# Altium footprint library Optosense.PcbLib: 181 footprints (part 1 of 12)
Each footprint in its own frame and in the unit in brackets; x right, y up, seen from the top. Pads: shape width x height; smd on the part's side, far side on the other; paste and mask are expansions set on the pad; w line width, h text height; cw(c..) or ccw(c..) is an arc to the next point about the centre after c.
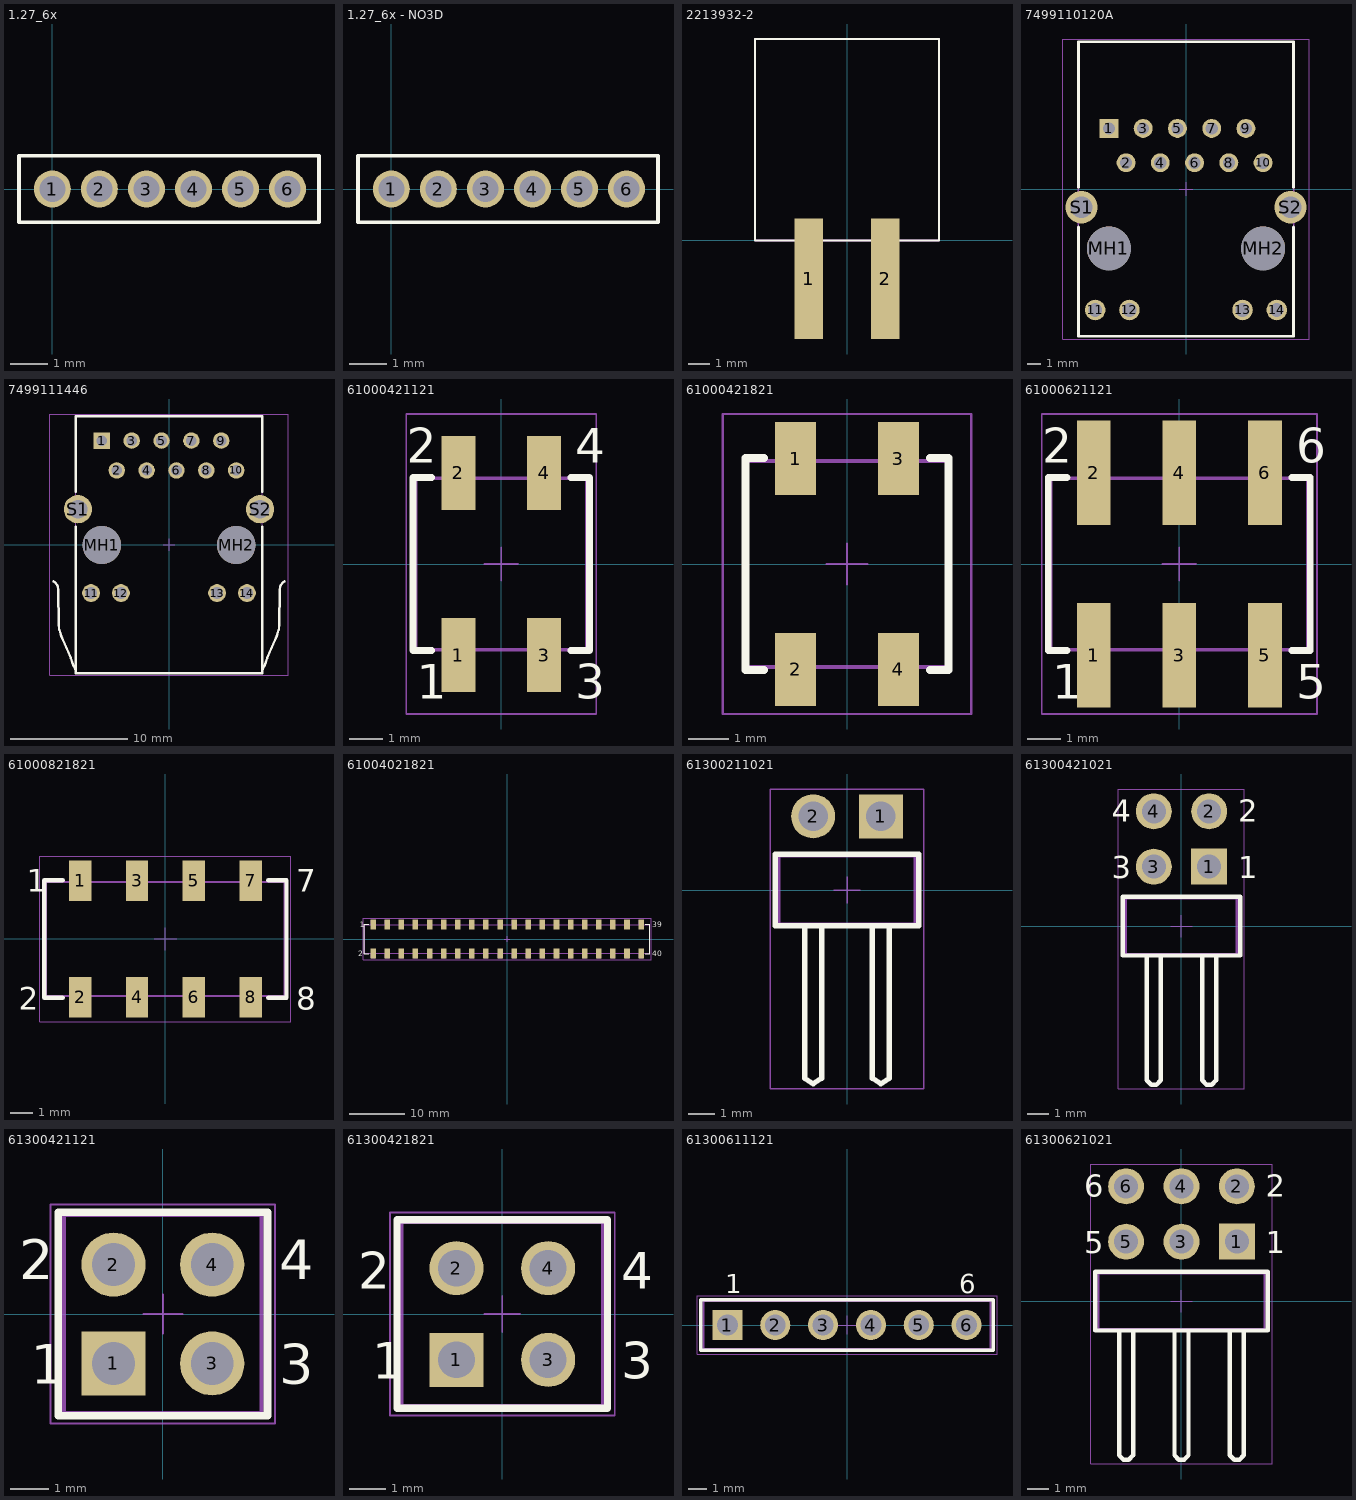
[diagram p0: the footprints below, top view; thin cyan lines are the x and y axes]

## 1.27_6x [mm]
pads (6):
  round 1 hole 0.7: 1(0,0) 2(1.27,0) 3(2.54,0) 4(3.81,0) 5(5.08,0) 6(6.35,0)
Top Overlay:
  lines w0.1: -0.9,-0.9 -0.9,0.9 ; -0.9,-0.9 7.2,-0.9 7.2,0.9 -0.9,0.9 ; -0.9,-0.9 -0.9,0.9
3D body "User Library-PLLR-6.step": height 2.35, standoff -2.45, extent -0.635,-0.2 6.985,6

## 1.27_6x - NO3D [mm]
pads (6):
  round 1 hole 0.7: 1(0,0) 2(1.27,0) 3(2.54,0) 4(3.81,0) 5(5.08,0) 6(6.35,0)
Top Overlay:
  lines w0.1: -0.9,-0.9 -0.9,0.9 ; -0.9,-0.9 7.2,-0.9 7.2,0.9 -0.9,0.9 ; -0.9,-0.9 -0.9,0.9

## 2213932-2 [mm]
pads (2):
  rect 1.3x5.5 smd paste+0 mask+0: 1(-1.75,-1.75) 2(1.75,-1.75)
Top Overlay:
  lines w0.1: -4.2,0 4.2,0 4.2,9.2 -4.2,9.2 -4.2,0
Mechanical 15:
  lines w0.1: -4.2,0 0,0 4.2,0 4.2,9.2 -4.2,9.2 -4.2,0
3D body "c-2213932-2-1-3d.stp": height 7.35, standoff 0.05, extent -4.2,-3.5 4.2,9.2

## 7499110120A [mm] "LAN Transformer, body 21.84x15.95mm"
height 16.9
pads (18):
  rect 1.4x1.4 hole 0.9: 1(-5.715,4.49)
  round 1.4 hole 0.9: 2(-4.445,1.95) 3(-3.175,4.49) 4(-1.905,1.95) 5(-0.635,4.49) 6(0.635,1.95) 7(1.905,4.49) 8(3.175,1.95) 9(4.445,4.49) 10(5.715,1.95)
  round 1.52 hole 1.02: 11(-6.73,-8.97) 12(-4.19,-8.97) 13(4.19,-8.97) 14(6.73,-8.97)
  round 3.25 hole 3.25 unplated: MH1(-5.715,-4.4) MH2(5.715,-4.4)
  round 2.4 hole 1.6: S1(-7.745,-1.35) S2(7.745,-1.35)
Top Overlay:
  lines w0.2: -7.975,-2.82 -7.975,-10.92 7.975,-10.92 7.975,-2.82 ; -7.975,0.12 -7.975,10.92 7.975,10.92 7.975,0.12
Mechanical 13:
  lines w0.1: -7.975,-10.92 7.975,-10.92 7.975,10.92 -7.975,10.92 -7.975,-10.92
Mechanical 15:
  lines w0.05: -0.5,0 0.5,0 ; 0,-0.5 0,0.5 ; -9.145,-11.12 -9.145,11.12 9.145,11.12 9.145,-11.12 -9.145,-11.12
3D body "7499110120A.stp": height 16.87, standoff -3.32, extent -8.1,-10.92 8.1,10.92

## 7499111446 [mm] "LAN Transformer, body 21.84x15.88mm"
height 13.95
pads (18):
  rect 1.4x1.4 hole 0.9: 1(-5.715,8.86)
  round 1.4 hole 0.9: 2(-4.445,6.32) 3(-3.175,8.86) 4(-1.905,6.32) 5(-0.635,8.86) 6(0.635,6.32) 7(1.905,8.86) 8(3.175,6.32) 9(4.445,8.86) 10(5.715,6.32)
  round 1.52 hole 1.02: 11(-6.63,-4.11) 12(-4.09,-4.11) 13(4.09,-4.11) 14(6.63,-4.11)
  round 3.25 hole 3.25 unplated: MH1(-5.715,-0.03) MH2(5.715,-0.03)
  round 2.4 hole 1.6: S1(-7.745,3.02) S2(7.745,3.02)
Top Overlay:
  lines w0.2: -9.83,-3.109 cw(c-10.225,-3.801) -9.428,-3.801 -9.37,-6.9 ccw(c-8.1,-6.9) -9.27,-7.394 ccw(c-6.8,-6.9) -9.012,-8.105 -8.345,-9.664 ccw(c-2,-7.78) -7.94,-10.7 ; -7.94,1.53 -7.94,-10.92 7.94,-10.92 7.94,1.53 ; -7.94,4.48 -7.94,10.92 7.94,10.92 7.94,4.48 ; 7.94,-10.7 ccw(c2,-7.78) 8.345,-9.664 9.012,-8.105 ccw(c6.8,-6.9) 9.27,-7.394 ccw(c8.1,-6.9) 9.37,-6.9 9.428,-3.801 cw(c10.225,-3.801) 9.83,-3.109
Mechanical 13:
  lines w0.1: -9.83,-3.109 cw(c-10.225,-3.801) -9.428,-3.801 -9.37,-6.9 ccw(c-8.1,-6.9) -9.27,-7.394 ccw(c-6.8,-6.9) -9.012,-8.105 -8.345,-9.664 ccw(c-2,-7.78) -7.94,-10.7 ; 7.94,-10.7 ccw(c2,-7.78) 8.345,-9.664 9.012,-8.105 ccw(c6.8,-6.9) 9.27,-7.394 ccw(c8.1,-6.9) 9.37,-6.9 9.428,-3.801 cw(c10.225,-3.801) 9.83,-3.109 ; -7.94,-10.92 -7.94,10.92 7.94,10.92 7.94,-10.92 -7.94,-10.92
Mechanical 15:
  lines w0.05: -0.5,0 0.5,0 ; 0,-0.5 0,0.5 ; -10.13,-11.12 -10.13,11.12 10.13,11.12 10.13,-11.12 -10.13,-11.12
3D body "7499111446.stp": height 16.01, standoff -3.52, extent -9.923,-10.92 9.923,10.92

## 61000421121 [mm] "Pin Header, pitch 2.54 mm, SMD, Vertical, dual row, 4p"
height 9.6
pads (4):
  rect 1x2.2 smd: 1(-1.27,-2.7) 2(-1.27,2.7) 3(1.27,-2.7) 4(1.27,2.7)
Top Overlay:
  lines w0.2: -2.065,-2.565 -2.615,-2.565 -2.615,2.565 -2.065,2.565 ; 2.065,-2.565 2.615,-2.565 2.615,2.565 2.065,2.565
  text "1" at -2.5,-4 h1.02
  text "3" at 2.2,-4 h1.02
  text "4" at 2.2,3 h1.02
  text "2" at -2.8,3 h1.02
Mechanical 13:
  lines w0.1: -1.59,-2.54 -1.59,-3.75 -0.95,-3.75 -0.95,-2.54 ; -1.59,2.54 -1.59,3.75 -0.95,3.75 -0.95,2.54 ; 0.95,-2.54 0.95,-3.75 1.59,-3.75 1.59,-2.54 ; 0.95,2.54 0.95,3.75 1.59,3.75 1.59,2.54 ; -2.54,-2.54 -2.54,2.54 2.54,2.54 2.54,-2.54 -2.54,-2.54
Mechanical 15:
  lines w0.05: -0.5,0 0.5,0 ; 0,-0.5 0,0.5 ; -2.815,-4.45 2.815,-4.45 2.815,4.45 -2.815,4.45 -2.815,-4.45
3D body "61000421121.stp": height 9.62, standoff 0.02, extent -2.54,-3.75 2.54,3.75

## 61000421821 [mm] "Socket Header, Pitch 2.54 mm, SMT, Vertical, dual row, 4p"
height 7.45
pads (4):
  rect 1x1.8 smd: 1(-1.27,2.6) 2(-1.27,-2.6) 3(1.27,2.6) 4(1.27,-2.6)
Top Overlay:
  lines w0.2: -2.05,-2.615 -2.5,-2.615 -2.5,2.615 -2.05,2.615 ; 2.05,-2.615 2.5,-2.615 2.5,2.615 2.05,2.615
Mechanical 13:
  lines w0.1: -1.59,-2.54 -1.59,-3.35 -0.95,-3.35 -0.95,-2.54 ; -1.59,2.54 -1.59,3.35 -0.95,3.35 -0.95,2.54 ; 0.95,-2.54 0.95,-3.35 1.59,-3.35 1.59,-2.54 ; 0.95,2.54 0.95,3.35 1.59,3.35 1.59,2.54 ; -2.5,-2.54 -2.5,2.54 2.5,2.54 2.5,-2.54 -2.5,-2.54
Mechanical 15:
  lines w0.05: -0.5,0 0.5,0 ; 0,-0.5 0,0.5 ; -3.065,-3.7 -3.065,3.7 3.065,3.7 3.065,-3.7 -3.065,-3.7
3D body "61000421821.stp": height 8.5, standoff 0, extent -2.54,-3.35 2.54,3.35

## 61000621121 [mm] "Pin Header, pitch 2.54 mm, SMD, Vertical, dual row, 6p"
height 9.6
pads (6):
  rect 1x3.1 smd: 1(-2.54,-2.7) 2(-2.54,2.7) 3(0,-2.7) 4(0,2.7) 5(2.54,-2.7) 6(2.54,2.7)
Top Overlay:
  lines w0.2: -3.335,-2.565 -3.885,-2.565 -3.885,2.565 -3.335,2.565 ; 3.335,-2.565 3.885,-2.565 3.885,2.565 3.335,2.565
  text "1" at -3.77,-4 h1.02
  text "2" at -4.07,3 h1.02
  text "5" at 3.47,-4 h1.02
  text "6" at 3.47,3 h1.02
Mechanical 13:
  lines w0.1: -2.86,-2.54 -2.86,-3.75 -2.22,-3.75 -2.22,-2.54 ; -2.86,2.54 -2.86,3.75 -2.22,3.75 -2.22,2.54 ; -0.32,-2.54 -0.32,-3.75 0.32,-3.75 0.32,-2.54 ; -0.32,2.54 -0.32,3.75 0.32,3.75 0.32,2.54 ; 2.22,-2.54 2.22,-3.75 2.86,-3.75 2.86,-2.54 ; 2.22,2.54 2.22,3.75 2.86,3.75 2.86,2.54 ; -3.81,-2.54 -3.81,2.54 3.81,2.54 3.81,-2.54 -3.81,-2.54
Mechanical 15:
  lines w0.05: -0.5,0 0.5,0 ; 0,-0.5 0,0.5 ; -4.085,-4.45 4.085,-4.45 4.085,4.45 -4.085,4.45 -4.085,-4.45
3D body "61000621121.stp": height 9.62, standoff 0.02, extent -3.81,-3.75 3.81,3.75

## 61000821821 [mm] "Socket Header, Pitch 2.54 mm, SMT, Vertical, dual row, 8p"
height 7.45
pads (8):
  rect 1x1.8 smd: 1(-3.81,2.6) 2(-3.81,-2.6) 3(-1.27,2.6) 4(-1.27,-2.6) 5(1.27,2.6) 6(1.27,-2.6) 7(3.81,2.6) 8(3.81,-2.6)
Top Overlay:
  lines w0.2: -4.59,-2.615 -5.405,-2.615 -5.405,2.615 -4.59,2.615 ; 4.59,-2.615 5.405,-2.615 5.405,2.615 4.59,2.615
  text "1" at -6.19,2.1 h1.02
  text "2" at -6.54,-3.15 h1.02
  text "7" at 5.84,2.1 h1.02
  text "8" at 5.84,-3.15 h1.02
Mechanical 13:
  lines w0.1: -4.13,-2.54 -4.13,-3.35 -3.49,-3.35 -3.49,-2.54 ; -4.13,2.54 -4.13,3.35 -3.49,3.35 -3.49,2.54 ; -1.59,-2.54 -1.59,-3.35 -0.95,-3.35 -0.95,-2.54 ; -1.59,2.54 -1.59,3.35 -0.95,3.35 -0.95,2.54 ; 0.95,-2.54 0.95,-3.35 1.59,-3.35 1.59,-2.54 ; 0.95,2.54 0.95,3.35 1.59,3.35 1.59,2.54 ; 3.49,-2.54 3.49,-3.35 4.13,-3.35 4.13,-2.54 ; 3.49,2.54 3.49,3.35 4.13,3.35 4.13,2.54 ; -5.33,-2.54 5.33,-2.54 5.33,2.54 -5.33,2.54 -5.33,-2.54
Mechanical 15:
  lines w0.05: -0.5,0 0.5,0 ; 0,-0.5 0,0.5 ; -5.605,-3.7 5.605,-3.7 5.605,3.7 -5.605,3.7 -5.605,-3.7
3D body "61000821821.stp": height 8.5, standoff 0, extent -5.08,-3.35 5.08,3.35

## 61004021821 [mm] "Socket Header, Pitch 2.54 mm, SMT, Vertical, dual row, 40p"
height 7.45
pads (40):
  rect 1x1.8 smd: 1(-24.13,2.6) 2(-24.13,-2.6) 3(-21.59,2.6) 4(-21.59,-2.6) 5(-19.05,2.6) 6(-19.05,-2.6) 7(-16.51,2.6) 8(-16.51,-2.6) 9(-13.97,2.6) 10(-13.97,-2.6) 11(-11.43,2.6) 12(-11.43,-2.6) 13(-8.89,2.6) 14(-8.89,-2.6) 15(-6.35,2.6) 16(-6.35,-2.6) 17(-3.81,2.6) 18(-3.81,-2.6) 19(-1.27,2.6) 20(-1.27,-2.6) 21(1.27,2.6) 22(1.27,-2.6) 23(3.81,2.6) 24(3.81,-2.6) 25(6.35,2.6) 26(6.35,-2.6) 27(8.89,2.6) 28(8.89,-2.6) 29(11.43,2.6) 30(11.43,-2.6) 31(13.97,2.6) 32(13.97,-2.6) 33(16.51,2.6) 34(16.51,-2.6) 35(19.05,2.6) 36(19.05,-2.6) 37(21.59,2.6) 38(21.59,-2.6) 39(24.13,2.6) 40(24.13,-2.6)
Top Overlay:
  lines w0.2: -24.91,-2.615 -25.725,-2.615 -25.725,2.615 -24.91,2.615 ; 24.91,-2.615 25.725,-2.615 25.725,2.615 24.91,2.615
  text "1" at -26.51,2.1 h1.02
  text "2" at -26.86,-3.15 h1.02
  text "39" at 26.16,2.1 h1.02
  text "40" at 26.16,-3.15 h1.02
Mechanical 13:
  lines w0.1: -24.45,-2.54 -24.45,-3.35 -23.81,-3.35 -23.81,-2.54 ; -24.45,2.54 -24.45,3.35 -23.81,3.35 -23.81,2.54 ; -21.91,-2.54 -21.91,-3.35 -21.27,-3.35 -21.27,-2.54 ; -21.91,2.54 -21.91,3.35 -21.27,3.35 -21.27,2.54 ; -19.37,-2.54 -19.37,-3.35 -18.73,-3.35 -18.73,-2.54 ; -19.37,2.54 -19.37,3.35 -18.73,3.35 -18.73,2.54 ; -16.83,-2.54 -16.83,-3.35 -16.19,-3.35 -16.19,-2.54 ; -16.83,2.54 -16.83,3.35 -16.19,3.35 -16.19,2.54 ; -14.29,-2.54 -14.29,-3.35 -13.65,-3.35 -13.65,-2.54 ; -14.29,2.54 -14.29,3.35 -13.65,3.35 -13.65,2.54 ; -11.75,-2.54 -11.75,-3.35 -11.11,-3.35 -11.11,-2.54 ; -11.75,2.54 -11.75,3.35 -11.11,3.35 -11.11,2.54 ; -9.21,-2.54 -9.21,-3.35 -8.57,-3.35 -8.57,-2.54 ; -9.21,2.54 -9.21,3.35 -8.57,3.35 -8.57,2.54 ; -6.67,-2.54 -6.67,-3.35 -6.03,-3.35 -6.03,-2.54 ; -6.67,2.54 -6.67,3.35 -6.03,3.35 -6.03,2.54 ; -4.13,-2.54 -4.13,-3.35 -3.49,-3.35 -3.49,-2.54 ; -4.13,2.54 -4.13,3.35 -3.49,3.35 -3.49,2.54 ; -1.59,-2.54 -1.59,-3.35 -0.95,-3.35 -0.95,-2.54 ; -1.59,2.54 -1.59,3.35 -0.95,3.35 -0.95,2.54 ; 0.95,-2.54 0.95,-3.35 1.59,-3.35 1.59,-2.54 ; 0.95,2.54 0.95,3.35 1.59,3.35 1.59,2.54 ; 3.49,-2.54 3.49,-3.35 4.13,-3.35 4.13,-2.54 ; 3.49,2.54 3.49,3.35 4.13,3.35 4.13,2.54 ; 6.03,-2.54 6.03,-3.35 6.67,-3.35 6.67,-2.54 ; 6.03,2.54 6.03,3.35 6.67,3.35 6.67,2.54 ; 8.57,-2.54 8.57,-3.35 9.21,-3.35 9.21,-2.54 ; 8.57,2.54 8.57,3.35 9.21,3.35 9.21,2.54 ; 11.11,-2.54 11.11,-3.35 11.75,-3.35 11.75,-2.54 ; 11.11,2.54 11.11,3.35 11.75,3.35 11.75,2.54 ; 13.65,-2.54 13.65,-3.35 14.29,-3.35 14.29,-2.54 ; 13.65,2.54 13.65,3.35 14.29,3.35 14.29,2.54 ; 16.19,-2.54 16.19,-3.35 16.83,-3.35 16.83,-2.54 ; 16.19,2.54 16.19,3.35 16.83,3.35 16.83,2.54 ; 18.73,-2.54 18.73,-3.35 19.37,-3.35 19.37,-2.54 ; 18.73,2.54 18.73,3.35 19.37,3.35 19.37,2.54 ; 21.27,-2.54 21.27,-3.35 21.91,-3.35 21.91,-2.54 ; 21.27,2.54 21.27,3.35 21.91,3.35 21.91,2.54 ; 23.81,-2.54 23.81,-3.35 24.45,-3.35 24.45,-2.54 ; 23.81,2.54 23.81,3.35 24.45,3.35 24.45,2.54 ; -25.65,-2.54 25.65,-2.54 25.65,2.54 -25.65,2.54 -25.65,-2.54
Mechanical 15:
  lines w0.05: -0.5,0 0.5,0 ; 0,-0.5 0,0.5 ; -25.925,-3.7 25.925,-3.7 25.925,3.7 -25.925,3.7 -25.925,-3.7
3D body "61004021821.stp": height 7.5, standoff 0, extent -25.4,-3.35 25.4,3.35

## 61300211021 [mm] "Pin Header, pitch 2.54 mm, THT, Angled, single row, 2p"
height 2.54
pads (2):
  rect 1.65x1.65 hole 1.1: 1(1.27,2.77)
  round 1.65 hole 1.1: 2(-1.27,2.77)
Top Overlay:
  lines w0.2: -1.59,-1.345 -1.59,-7.07 -1.27,-7.27 -0.95,-7.07 -0.95,-1.345 ; 0.95,-1.345 0.95,-7.07 1.27,-7.27 1.59,-7.07 1.59,-1.345 ; -2.69,-1.345 -2.69,1.345 2.69,1.345 2.69,-1.345 -2.69,-1.345
Mechanical 13:
  lines w0.1: -1.59,-1.27 -1.59,-7.07 -1.27,-7.27 -0.95,-7.07 -0.95,-1.27 ; 0.95,-1.27 0.95,-7.07 1.27,-7.27 1.59,-7.07 1.59,-1.27 ; -2.54,-1.27 -2.54,1.27 2.54,1.27 2.54,-1.27 -2.54,-1.27
Mechanical 15:
  lines w0.05: -0.5,0 0.5,0 ; 0,-0.5 0,0.5 ; -2.89,-7.47 -2.89,3.795 2.89,3.795 2.89,-7.47 -2.89,-7.47
3D body "61300211021.stp": height 2.58, standoff -2.96, extent -2.54,-7.27 2.54,3.09

## 61300421021 [mm] "Pin Header, pitch 2.54 mm, THT, Angled, dual row, 4p"
height 5.08
pads (4):
  rect 1.65x1.65 hole 1.1: 1(1.27,2.73)
  round 1.65 hole 1.1: 2(1.27,5.27) 3(-1.27,2.73) 4(-1.27,5.27)
Top Overlay:
  lines w0.2: -1.59,-1.345 -1.59,-7.07 -1.39,-7.27 -1.15,-7.27 -0.95,-7.07 -0.95,-1.345 ; 0.95,-1.345 0.95,-7.07 1.15,-7.27 1.39,-7.27 1.59,-7.07 1.59,-1.345 ; -2.69,-1.345 -2.69,1.345 2.69,1.345 2.69,-1.345 -2.69,-1.345
  text "1" at 2.6,2.2 h1.02
  text "2" at 2.6,4.8 h1.02
  text "4" at -3.2,4.8 h1.02
  text "3" at -3.2,2.2 h1.02
Mechanical 13:
  lines w0.1: -1.59,-1.27 -1.59,-7.07 -1.39,-7.27 -1.15,-7.27 -0.95,-7.07 -0.95,-1.27 ; 0.95,-1.27 0.95,-7.07 1.15,-7.27 1.39,-7.27 1.59,-7.07 1.59,-1.27 ; -2.54,-1.27 2.54,-1.27 2.54,1.27 -2.54,1.27 -2.54,-1.27
Mechanical 15:
  lines w0.05: -0.5,0 0.5,0 ; 0,-0.5 0,0.5 ; -2.89,-7.47 -2.89,6.295 2.89,6.295 2.89,-7.47 -2.89,-7.47
3D body "61300421021.stp": height 5.12, standoff -2.96, extent -2.54,-7.27 2.54,5.63

## 61300421121 [mm] "Pin Header, pitch 2.54 mm, THT, Vertical, dual row, 4p"
height 8.54
pads (4):
  rect 1.65x1.65 hole 1.1: 1(-1.27,-1.27)
  round 1.65 hole 1.1: 2(-1.27,1.27) 3(1.27,-1.27) 4(1.27,1.27)
Top Overlay:
  lines w0.2: -2.69,-2.615 -2.69,2.615 2.69,2.615 2.69,-2.615 -2.69,-2.615
  text "1" at -3.4,-1.8 h1.02
  text "2" at -3.7,0.9 h1.02
  text "3" at 3,-1.8 h1.02
  text "4" at 3,0.9 h1.02
Mechanical 13:
  lines w0.1: -2.54,-2.54 -2.54,2.54 2.54,2.54 2.54,-2.54 -2.54,-2.54
Mechanical 15:
  lines w0.05: -0.5,0 0.5,0 ; 0,-0.5 0,0.5 ; -2.89,-2.815 2.89,-2.815 2.89,2.815 -2.89,2.815 -2.89,-2.815
3D body "61300421121.stp": height 8.59, standoff -2.95, extent -2.54,-2.54 2.54,2.54

## 61300421821 [mm] "Socket Header, Pitch 2.54 mm, THT, Vertical, dual row, 4p"
height 8.4
pads (4):
  rect 1.5x1.5 hole 1.02: 1(-1.27,-1.27)
  round 1.5 hole 1.02: 2(-1.27,1.27) 3(1.27,-1.27) 4(1.27,1.27)
Top Overlay:
  lines w0.2: -2.915,-2.615 2.915,-2.615 2.915,2.615 -2.915,2.615 -2.915,-2.615
  text "1" at -3.6,-1.8 h1.02
  text "3" at 3.3,-1.8 h1.02
  text "2" at -4,0.7 h1.02
  text "4" at 3.3,0.7 h1.02
Mechanical 13:
  lines w0.1: -2.79,-2.54 -2.79,2.54 2.79,2.54 2.79,-2.54 -2.79,-2.54
Mechanical 15:
  lines w0.05: -0.5,0 0.5,0 ; 0,-0.5 0,0.5 ; -3.115,-2.815 -3.115,2.815 3.115,2.815 3.115,-2.815 -3.115,-2.815
3D body "61300421821.stp": height 8.45, standoff -3.05, extent -2.79,-2.54 2.79,2.54

## 61300611121 [mm] "Pin Header, pitch 2.54 mm, THT, Vertical, single row, 6p"
height 8.54
pads (6):
  rect 1.6x1.6 hole 1.1: 1(-6.35,0)
  round 1.6 hole 1.1: 2(-3.81,0) 3(-1.27,0) 4(1.27,0) 5(3.81,0) 6(6.35,0)
Top Overlay:
  lines w0.2: -7.77,-1.345 -7.77,1.345 7.77,1.345 7.77,-1.345 -7.77,-1.345
  text "6" at 5.97,1.7 h1.02
  text "1" at -6.47,1.7 h1.02
Mechanical 13:
  lines w0.1: -7.62,-1.27 7.62,-1.27 7.62,1.27 -7.62,1.27 -7.62,-1.27
Mechanical 15:
  lines w0.05: -0.5,0 0.5,0 ; 0,-0.5 0,0.5 ; -7.97,-1.545 7.97,-1.545 7.97,1.545 -7.97,1.545 -7.97,-1.545
3D body "61300611121.stp": height 8.57, standoff -2.97, extent -7.62,-1.27 7.62,1.27

## 61300621021 [mm] "Pin Header, pitch 2.54 mm, THT, Angled, dual row, 6p"
height 5.08
pads (6):
  rect 1.65x1.65 hole 1.1: 1(2.54,2.73)
  round 1.65 hole 1.1: 2(2.54,5.27) 3(0,2.73) 4(0,5.27) 5(-2.54,2.73) 6(-2.54,5.27)
Top Overlay:
  lines w0.2: -2.86,-1.345 -2.86,-7.07 -2.66,-7.27 -2.42,-7.27 -2.22,-7.07 -2.22,-1.345 ; -0.32,-1.345 -0.32,-7.07 -0.12,-7.27 0.12,-7.27 0.32,-7.07 0.32,-1.345 ; 2.22,-1.345 2.22,-7.07 2.42,-7.27 2.66,-7.27 2.86,-7.07 2.86,-1.345 ; -3.96,-1.345 -3.96,1.345 3.96,1.345 3.96,-1.345 -3.96,-1.345
  text "6" at -4.47,4.8 h1.02
  text "5" at -4.47,2.2 h1.02
  text "1" at 3.87,2.2 h1.02
  text "2" at 3.87,4.8 h1.02
Mechanical 13:
  lines w0.1: -2.86,-1.27 -2.86,-7.07 -2.66,-7.27 -2.42,-7.27 -2.22,-7.07 -2.22,-1.27 ; -0.32,-1.27 -0.32,-7.07 -0.12,-7.27 0.12,-7.27 0.32,-7.07 0.32,-1.27 ; 2.22,-1.27 2.22,-7.07 2.42,-7.27 2.66,-7.27 2.86,-7.07 2.86,-1.27 ; -3.81,-1.27 3.81,-1.27 3.81,1.27 -3.81,1.27 -3.81,-1.27
Mechanical 15:
  lines w0.05: -0.5,0 0.5,0 ; 0,-0.5 0,0.5 ; -4.16,-7.47 -4.16,6.295 4.16,6.295 4.16,-7.47 -4.16,-7.47
3D body "61300621021.stp": height 5.12, standoff -2.96, extent -3.81,-7.27 3.81,5.63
